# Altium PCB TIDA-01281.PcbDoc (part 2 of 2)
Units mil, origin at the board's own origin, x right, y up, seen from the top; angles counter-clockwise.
Board outline 2559.06 x 2165.35 mil, 4 copper layers (Top Layer, GND, SIGNAL, Bottom Layer), stack 60.234 mil thick; 109 components, 85 nets, 348 pads, 231 vias.
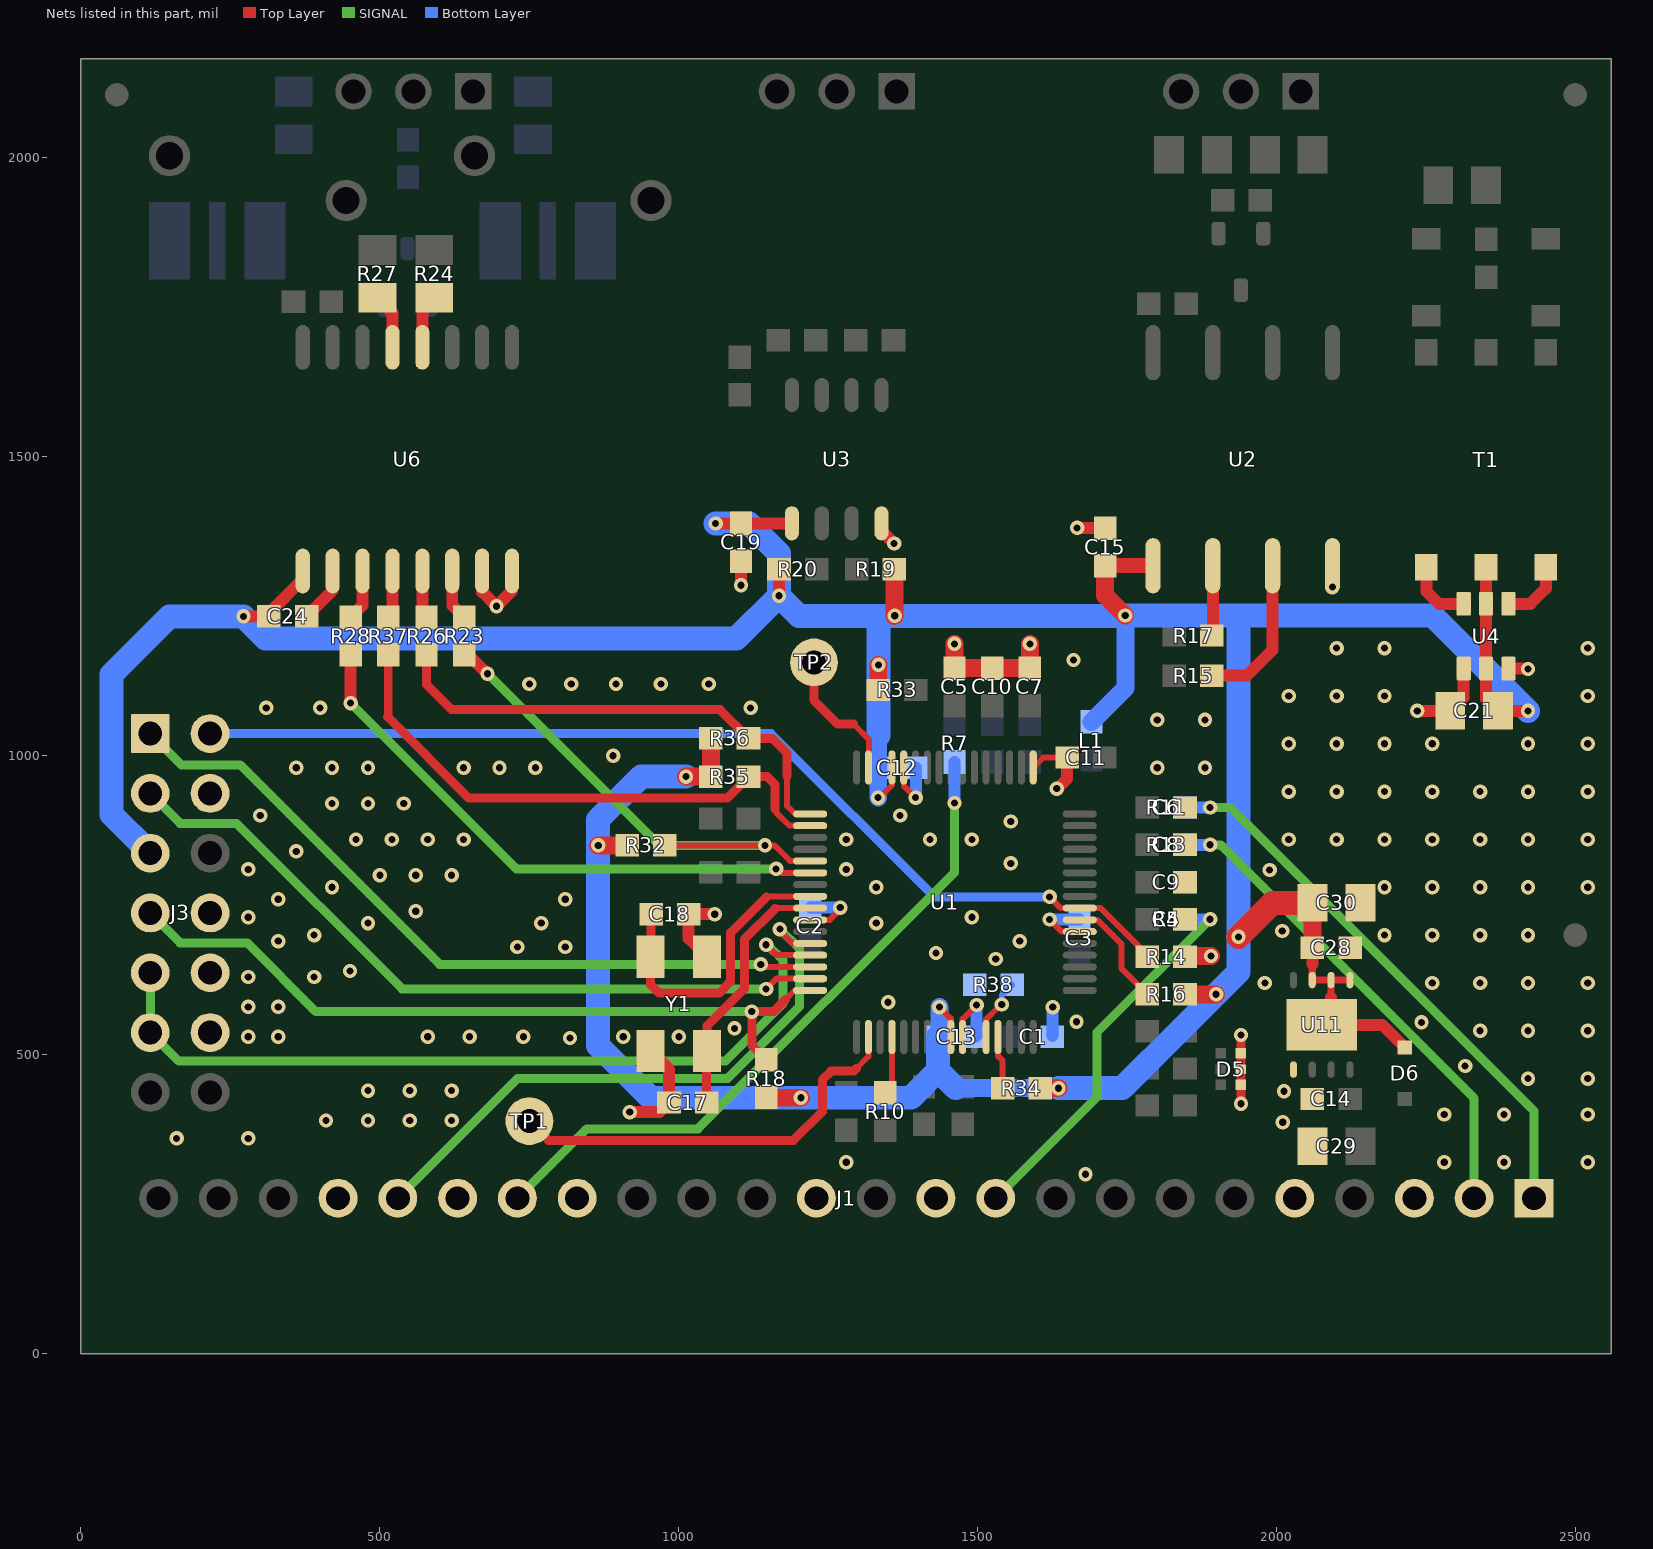
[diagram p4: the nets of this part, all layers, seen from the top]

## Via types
v1: diameter 24, hole 12, Top Layer to Bottom Layer, 231 vias

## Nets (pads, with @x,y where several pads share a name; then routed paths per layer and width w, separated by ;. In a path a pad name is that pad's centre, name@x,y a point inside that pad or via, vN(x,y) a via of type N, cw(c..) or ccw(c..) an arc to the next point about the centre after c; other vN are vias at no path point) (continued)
NetR10_1: R10.1 U1.52 | length 97.8
  Top Layer w10: R10.1@1345,436.5 1356.42,447.91 U1.52@1356.42,529.61
NetR15_2: R15.2 U2.3 | length 260.2
  Top Layer w20: R15.2@1891.5,1134 1950,1134 1993,1177 U2.3@1993,1317.85
NetR16_1: R16.1 U1.7 | length 188.6
  Top Layer w10: U1.7@1670.39,725.47 1699.91,725.47 1740,685.38 1740,644.5 R16.1@1783.5,601
NetR17_2: R17.2 U2.2 | length 117.5
  Top Layer w20: R17.2@1891.5,1201 1893,1202.51 U2.2@1893,1317.85
NetR23_1: R23.1 U6.6 | length 85.8
  Top Layer w20: U6.6@621,1308.99 621,1251.5 R23.1@641,1231.5
NetR24_1: R24.1 U6.12 | length 91.3
  Top Layer w20: U6.12@571,1683.01 571,1746 R24.1@591,1766
NetR26_1: R26.1 U6.5 | length 80.4
  Top Layer w20: U6.5@571,1308.99 571,1238.5 R26.1@578,1231.5
NetR27_1: R27.1 U6.13 | length 93.3
  Top Layer w20: R27.1@496,1766 521,1741 U6.13@521,1683.01
NetR28_1: R28.1 U6.3 | length 85.8
  Top Layer w20: R28.1@451,1231.5 471,1251.5 U6.3@471,1308.99
NetR34_1: R34.1 U1.61 | length 88.9
  Top Layer w10: U1.61@1533.58,529.61 1533.58,498.32 1541.5,490.4 R34.1@1541.5,444
NetR37_1: R37.1 U6.4 | length 80.4
  Top Layer w20: R37.1@514,1231.5 521,1238.5 U6.4@521,1308.99
NetR38_1: R38.1 U1.60 | length 109.2
  Top Layer w10: U1.60@1513.9,529.61 1513.9,559.26 1533.64,579 1534,579 v1@1536,581 ; v1@1538,582 v1@1537,582 ; v1(1540,584) 1539,584 v1@1537,582 ; v1@1536,581 1536,582 v1@1537,582 ; v1@1536,581 v1@1537,582
  Bottom Layer w10: v1(1540,584) 1540,599.5 R38.1@1557.5,617
NetT1_1: T1.1 U4.3 | length 111.3
  Top Layer w20: T1.1@2250,1315.08 2250,1275 2270.87,1254.13 U4.3@2312.6,1254.13
NetT1_3: T1.3 U4.1 | length 108.4
  Top Layer w20: U4.1@2387.4,1254.13 2424.13,1254.13 2450,1280 T1.3@2450,1315.08
NetTP1_1: TP1.1 U1.50 | length 706.5
  Top Layer w10: 1297,477 1317.05,497.05 U1.50@1317.05,529.61
  Top Layer w15: TP1.1@750,389 782.37,356.63 1191.63,356.63 1240,405 1240,458 1254.63,472.63 1292.63,472.63 1297,477 ; TP1.1@750,395 TP1.1@753,392
NetTP2_1: TP2.1 U1.31 | length 229.1
  Top Layer w10: 1292,1053 1317.74,1027.26 1317.74,981.08 U1.31@1317.05,980.39
  Top Layer w15: TP2.1@1226,1156 1226,1093 1266,1053 1292,1053
RS485_DE: R35.2 R37.2 U1.34 | length 940.9
  Top Layer w10: 1163.13,910.72 1163.13,904.88 1185.05,882.95 U1.34@1219.61,882.95
  Top Layer w15: R37.2@514,1168.5 514,1066 513,1065 649,929 1027.38,929 1027.45,929.08 1080.57,929.08 R35.2@1116.5,965 1147.63,965 1160.63,952 1160.63,910.72
RS485_REN: R26.2 R36.2 U1.33 | length 832.3
  Top Layer w10: 1181,966 1181,916 1194.36,902.64 U1.33@1219.61,902.64
  Top Layer w15: R26.2@578,1168.5 578,1119 620,1077 1068.5,1077 R36.2@1116.5,1029 1156,1029 1181,1004 1181,966
RS485_RX: R28.2 U1.38 | length 973.5
  Top Layer w10: v1@1162.71,817.3 v1(1162.71,810.71) 1163,811 1166,811 1172.79,804.21 U1.38@1219.61,804.21
  Top Layer w20: v1(451,1088) R28.2@451,1168.5
  SIGNAL w15: v1(451,1088) 728.29,810.71 v1(1162.71,810.71)
RS485_TX: R23.2 R32.2 U1.37 | length 888.9
  Top Layer w10: R32.2@976.5,850 v1(1144,850) 1160,850 1186.1,823.9 U1.37@1219.61,823.9
  Top Layer w20: R23.2@641,1168.5 647.99,1168.5 679.5,1137 v1(680,1137)
  SIGNAL w15: v1(680,1137) 967,850 v1(1144,850)
SGND: C1.2 C2.2 C3.1 C4.2 C5.2 C6.2 C7.2 C8.2 C9.2 C10.2 C11.2 C12.2 C13.2 C14.1 C15.2 C17.2 C18.2 C19.2 C21.1 C24.2 C28.1 C29.1 C30.1 D5.4 D5.5 D5.6 J1.3 J1.5 J1.11 J1.13 J1.17 J1.19 J1.21 J3.4 J3.8 J3.10 J3.12 R14.2 R38.2 U1.6 U1.17 U1.28 U1.42 U1.58 U2.4 U3.4 U4.4 U4.6 U6.2 U6.7 U6.8 U11.1 Y1.2 Y1.4 | length 1918.8
  Top Layer w8: v1@1266,746 v1(1270,746) v1@1270,743
  Top Layer w10: U1.42@1219.61,725.47 1252.47,725.47 v1@1270,743 ; U1.28@1376.1,980.39 1376.1,949.9 v1(1396,930) ; U1.58@1474.53,529.61 1474.53,559.12 ; v1@1495.02,579.61 1474.53,559.12 ; v1(1498,583) 1474.53,559.53 1474.53,559.12 ; U1.17@1592.64,980.39 1609.24,997 C11.2@1649.5,997 ; v1(1620,726) 1640.21,705.79 U1.6@1670.39,705.79
  Top Layer w15: v1(1940,418) 1940,449.16 D5.4@1939.73,449.43 D5.5@1939.73,476 D5.6@1939.73,502.57 1940,502.84 v1(1940,533)
  Top Layer w20: C24.2@377.5,1233 421,1276.51 U6.2@421,1308.99 ; U6.7@671,1308.99 671,1274 v1(695,1250) 721,1276 U6.8@721,1308.99 ; v1(918,404) 967.5,404 C17.2@983.5,420 983.5,475.51 Y1.4@952.76,506.26 ; Y1.2@1047.25,663.74 1016.5,694.49 C18.2@1016.5,735 v1(1060,735) ; v1(1104,1285) C19.2@1104,1325.51 ; U3.4@1339,1388.72 1339,1376 v1(1360,1355) ; v1(1632,945) v1@1633,945 ; v1@1634,945 v1@1633,945 ; C11.2@1649.5,997 1649.5,961.5 v1@1633,945 ; v1(1666.01,1381) 1665.5,1380.5 C15.2@1713,1380.5 ; v1(2093,1282) U2.4@2093,1352.85 ; v1(2235,1075) C21.1@2290,1075 2312.6,1097.6 U4.4@2312.6,1145.87 ; U4.6@2387.4,1145.87 2419.13,1145.87 v1(2420,1145)
  Top Layer w30: v1(1461,1187) C5.2@1461,1146.5 C10.2@1524,1146.5 C7.2@1587,1146.5 v1(1587,1187) ; R14.2@1846.5,664 1847.5,665 v1(1890,665)
  Bottom Layer w10: C13.2@1498.15,529.61 C13.2@1498.15,530
  Bottom Layer w20: C2.2@1220,746.5 1269.5,746.5 v1(1270,746) ; v1@1396.5,930.5 C12.2@1396.5,980 ; C13.2@1496.5,530 1498,531.5 v1(1498,583) ; v1(1620,726) 1620.5,726.5 C3.1@1670,726.5 ; C1.2@1625.13,531 v1@1625.13,579.45
  other v1: 1680,300 1280,320 2280,320 2380,320 2520,320 160,360 280,360 2010,387 410,390 480,390 550,390 620,390 2280,400 2380,400 2520,400 2012,439 480,440 550,440 620,440 2420,460 2520,460 2315,481 818,528 280,530 330,530 580,530 650,530 740,530 907,530 1000,530 2340,540 2420,540 2520,540 1093,544 2242,554 1665,555 1625.29,579.61 280,580 330,580 1350,587.68 1980,620 2260,620 2340,620 2420,620 2520,620 280,630 390,630 450,640 1530,660 1430,670 730,680 810,680 330,690 1570,690 390,700 2180,700 2260,700 2340,700 2420,700 2009,707 480,720 770,720 1330,720 280,730 1490,730 560,740 330,760 810,760 420,780 1330,780 2180,780 2260,780 2340,780 2420,780 2520,780 500,800 560,800 620,800 1988,809 280,810 1280,810 1555,820 360,840 460,860 520,860 580,860 640,860 1280,860 1420,860 1490,860 2020,860 2100,860 2180,860 2260,860 2340,860 2420,860 2520,860 1555,890 300,900 1370,900 420,920 480,920 540,920 2020,940 2100,940 2180,940 2260,940 2340,940 2420,940 2520,940 360,980 420,980 480,980 640,980 700,980 760,980 1800,980 1880,980 890,1000 2020,1020 2100,1020 2180,1020 2260,1020 2420,1020 2520,1020 1800,1060 1880,1060 310,1080 400,1080 1120,1080 2020,1100 2100,1100 2180,1100 2520,1100 750,1120 820,1120 895,1120 970,1120 1050,1120 1660,1160 2100,1180 2180,1180 2520,1180
TCK: J3.9 J3.11 U1.45 | length 1410.4
  Top Layer w10: v1(1146,684) 1163.58,666.42 U1.45@1219.61,666.42
  SIGNAL w15: J3.9@116,637 J3.11@116,537 163.86,489.15 1077.86,489.15 1174.37,585.66 1174.37,657.75 1148.13,684 v1(1146,684)
TDI: J3.3 U1.47 | length 1246.1
  Top Layer w10: v1(1146,610) 1163.05,627.05 U1.47@1219.61,627.05
  SIGNAL w15: J3.3@116,937 166,887 260,887 537,610 v1(1146,610)
TDO: J3.7 R18.1 U1.48 | length 1260.9
  Top Layer w10: 1178,592 1193.36,607.36 U1.48@1219.61,607.36
  Top Layer w15: v1(1122,572) 1122,515.5 R18.1@1139.5,498 ; v1@1129,572 1158.13,572 1178.06,591.94
  SIGNAL w15: J3.7@116,737 166,687 278,687 393,572 v1(1122,572)
TEMP1: J1.10 R5.1 | length 656.9
  SIGNAL w15: J1.10@1530,260 1699.13,429.13 1699.13,537.13 v1(1888.46,726.46)
  Bottom Layer w20: R5.1@1846.5,726.46 v1(1888.46,726.46)
TEMP2: J1.20 U1.44 | length 1009.9
  Top Layer w10: v1(1169,710) 1169,707 1189.9,686.1 U1.44@1219.61,686.1
  SIGNAL w15: J1.20@530,260 730.37,460.37 1081.44,460.37 1202,580.94 1202,677 v1(1169,710)
TMS: J3.1 U1.46 | length 1265.3
  Top Layer w10: v1(1137,651) 1141.27,646.73 U1.46@1219.61,646.73
  SIGNAL w15: J3.1@116,1037 168.15,984.86 266.14,984.86 600,651 v1(1137,651)
TRST: J3.2 R14.1 U1.8 | length 1737
  Top Layer w10: v1(1620,764) 1638.84,745.16 U1.8@1670.39,745.16 1705.5,745.16 R14.1@1795,655.66
  Bottom Layer w15: J3.2@216,1037 1154,1037 1427,764 v1(1620,764)
VBAT_S: J1.1 R11.1 | length 939.7
  SIGNAL w15: v1(1888.46,913.46) 1922.54,913.46 2430,406 J1.1@2430,260
  Bottom Layer w20: R11.1@1846.5,913.46 v1(1888.46,913.46)
VBOOST_S: J1.2 R13.1 | length 826.1
  SIGNAL w15: v1(1888.46,851) 1906,851 2330,427 J1.2@2330,260
  Bottom Layer w20: R13.1@1846.5,851 v1(1888.46,851)
VBUS_S: J1.18 R7.1 | length 1141.2
  SIGNAL w15: J1.18@730,260 846,376 1032,376 1461,805 v1(1461,921)
  Bottom Layer w20: v1(1461,921) R7.1@1461,989.5
VDD: C12.1 C13.1 C15.1 C19.1 C21.2 C24.1 C28.2 C30.2 D6.2 J3.5 L1.1 R16.2 R18.2 R19.1 R20.1 R32.1 R33.1 R34.2 R35.1 R36.1 T1.2 U1.29 U1.57 U2.1 U3.1 U4.2 U4.5 U6.1 U11.5 U11.6 U11.7 U11.9 | length 7961
  Top Layer w10: v1(1333.01,930) 1335.54,930 1356.42,950.88 U1.29@1356.42,980.39 ; v1(1435.65,579.61) 1454.84,560.42 U1.57@1454.84,529.61 ; C30.2@2059.5,753.5 C30.2@2060,754 ; U11.9@2088,550 2090.75,552.75 U11.9@2090.75,565.75
  Top Layer w12: 2059.25,651.73 U11.7@2059.25,624.8 U11.6@2090.75,624.8 ; 2090.75,596 U11.6@2090.75,624.8 ; U11.5@2122.24,624.8 U11.6@2090.75,624.8
  Top Layer w20: v1(272,1233) C24.1@314.5,1233 314.5,1238.5 371,1295 U6.1@371,1308.99 ; v1(1061.5,1388.5) C19.1@1104,1388.5 1104.22,1388.72 U3.1@1189,1388.72 ; v1(1167.5,1267.5) R20.1@1167.5,1312 ; C15.1@1713,1317.5 C15.1@1713.35,1317.85 ; U2.1@1793,1317.85 U2.1@1793,1352.85 ; 2059.25,651.73 2059.5,651.99 C28.2@2059.5,679 ; U11.9@2075,550 2090.75,565.75 2090.75,596 ; U11.9@2088,550 2176.31,550 D6.2@2214,512.31 ; T1.2@2350,1315.08 U4.2@2350,1254.13 U4.5@2350,1145.87 2350,1095 C21.2@2370,1075 v1(2420,1075)
  Top Layer w25: C15.1@1713.35,1317.85 U2.1@1793,1317.85
  Top Layer w30: v1(865.06,850) R32.1@913.5,850 ; v1(1012,965) R35.1@1053.5,965 R36.1@1053.5,1029 ; R18.2@1146,428.51 1146.51,428 v1(1204,428) ; R33.1@1333.5,1110 1333.5,1151.5 v1(1334,1152) ; R19.1@1360.5,1312 1360.5,1234.5 v1(1361,1234) ; v1@1624.5,444 v1(1635,444) ; C15.1@1713,1317.5 1713,1267.99 v1(1746.5,1234.5) ; R16.2@1846.5,601 v1(1898.54,601) ; C28.2@2059.5,679 C30.2@2059.5,753.5
  Top Layer w40: v1(1936,697) 1993,754 C30.2@2060,754
  Bottom Layer w20: 1842.54,545 1842.69,545
  Bottom Layer w25: C13.1@1433.5,530 C13.1@1435.65,532.15
  Bottom Layer w30: v1@1333.5,930.5 C12.1@1333.5,980 1333.5,1033.5 ; C13.1@1435.65,532.15 v1(1435.65,579.61) ; 1463.01,444 v1(1635,444) ; L1.1@1690,1056.5 1746.87,1113.37 1746.87,1234.12 v1(1746.5,1234.5)
  Bottom Layer w40: J3.5@116,837 51,902 51,1136 148,1233 v1(272,1233) 309,1196 1096,1196 v1(1167.5,1267.5) ; v1(1012,965) 937.06,965 865.06,893 v1(865.06,850) 865.06,515.55 952.61,428 1388,428 1433.5,473.5 ; v1(1061.5,1388.5) 1117.5,1388.5 1167.5,1338.5 v1(1167.5,1267.5) ; 1333.5,1033.5 1334,1034 v1(1334,1152) 1334,1233 1333,1234 ; C13.1@1433.5,530 1433.5,473.5 ; 1463.01,444 1433.5,473.5 ; v1(1635,444) 1695,444 1741.54,444 1842.54,545 v1(1898.54,601) 1936,638.46 v1(1936,697) 1936,1229.5 1941,1234.5 ; v1(2420,1075) 2260.5,1234.5 1941,1234.5 ; v1(1167.5,1267.5) 1201,1234 1333,1234 ; 1333,1234 v1(1361,1234) 1746,1234 v1(1746.5,1234.5) 1941,1234.5
X1: C17.1 U1.41 Y1.1 | length 430.9
  Top Layer w10: 1160.81,744.81 1161.16,745.16 U1.41@1219.61,745.16
  Top Layer w15: C17.1@1046.5,420 1046.5,505.51 Y1.1@1047.25,506.26 1047.25,548.25 1109.63,610.63 1109.63,692.94 1161.16,744.47
X2: C18.1 U1.40 Y1.3 | length 505.9
  Top Layer w10: 1146.5,764.5 1146.84,764.84 U1.40@1219.61,764.84
  Top Layer w15: C18.1@953.5,735 953.5,664.49 Y1.3@952.76,663.74 952.76,617.25 967,603 1067.3,603 1086.75,622.45 1086.75,704.06 1146.84,764.15
pads on no net: FID1.1 FID2.1 FID3.1 FID4.1 FID5.1 FID6.1 J3.6 J3.13 J3.14 U1.4 U1.9 U1.14 U1.15 U1.18 U1.19 U1.21 U1.24 U1.30 U1.36 U1.53 U1.55 U1.62 U1.63 U1.64 U5.2 U6.11 U6.14 U7.2 U11.8

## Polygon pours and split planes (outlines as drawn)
SGND on GND "M9 Title Sheet-No Net" (solid, remove dead copper, pour order 12): 0,235 0,75 75,0 1925,0 2469.06,0 2559.06,90 2559.06,1364.95 2503,1421 58,1421 0,1363
COMM_GND on GND "M9 Title Sheet-No Net" (solid, remove dead copper, pour order 16): 155,2165 70,2165 0,2095 0,1636 63,1573 2486,1573 2559.06,1646.06 2559.06,2095.95 2490,2165
SGND on Top Layer "M9 Title Sheet-No Net" (solid, remove dead copper, pour order 11): 0,235 0,75 75,0 1925,0 2469.06,0 2559.06,90 2559.06,1364.95 2503,1421 58,1421 0,1363
COMM_GND on Top Layer "M9 Title Sheet-No Net" (solid, remove dead copper, pour order 15): 155,2165 70,2165 0,2095 0,1636 63,1573 2486,1573 2559.06,1646.06 2559.06,2095.95 2490,2165
SGND on SIGNAL "M9 Title Sheet-No Net" (solid, remove dead copper, pour order 10): 0,235 0,75 75,0 1925,0 2469.06,0 2559.06,90 2559.06,1364.95 2503,1421 58,1421 0,1363
COMM_GND on SIGNAL "M9 Title Sheet-No Net" (solid, remove dead copper, pour order 14): 155,2165 70,2165 0,2095 0,1636 63,1573 2486,1573 2559.06,1646.06 2559.06,2095.95 2490,2165
SGND on Bottom Layer "M9 Title Sheet-No Net" (solid, remove dead copper, pour order 9): 0,235 0,75 75,0 1925,0 2469.06,0 2559.06,90 2559.06,1364.95 2503,1421 58,1421 0,1363
COMM_GND on Bottom Layer "M9 Title Sheet-No Net" (solid, remove dead copper, pour order 13): 155,2165 70,2165 0,2095 0,1636 63,1573 2486,1573 2559.06,1646.06 2559.06,2095.95 2490,2165

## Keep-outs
Keep-Out Layer:
  lines w10: 2558.11,0 2559.06,0.94 ; 0,0 0,2165.36 2559.06,2165.36 2559.06,0 0,0 ; 4730,3149.49 cw(c4730,3144.49) 4735,3144.49 ccw(c4730,3144.49) 4730,3149.49

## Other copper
Top Layer:
  text ".Layer_Name" at 357,-1164 h60
GND:
  text ".layer_Name" at 350,-1160 h60
SIGNAL:
  text ".layer_Name" at 360,-1160 h60
Bottom Layer:
  text ".Layer_Name" at 357,-1164 h60

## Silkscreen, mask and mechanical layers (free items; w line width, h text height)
Top Overlay:
  lines w6: 1884,576 1889,576 1891,576 ; 1909,407 1909,424 ; 2002,412 2020,412 ; 2385,1899 2409,1923 2421,1923 ; 1892,435 1953,435 1954,435 1954,516 1954,517 1892,517 1892,496 1892,435
  text "TIDA-01281-E1" at 1093,29 h60
  text ".Layer_Name" at 357,-1164 h60
Bottom Overlay:
  circle w10: c2490,260 r10
  text ".Layer_Name" at 357,-1164 h60
Top Paste:
  text ".Layer_Name" at 357,-1164 h60
Bottom Paste:
  text ".Layer_Name" at 357,-1164 h60
Top Solder:
  text ".Layer_Name" at 357,-1164 h60
  text ".Layer_Name" at 357,-1164 h60
Bottom Solder:
  text ".Layer_Name" at 357,-1164 h60
M1 Board Outline:
  the board outline again, w10
M2 Board Dimensions:
  rectangle: -95,-705.51 280,-580.51
  rectangle: -220,-580.51 -95,-455.51
  lines w7: -220,-580.51 780,-580.51 ; -95,-705.51 -95,-455.51 ; 30,-705.51 30,-455.51 ; 280,-705.51 280,-455.51 ; 530,-705.51 530,-455.51 ; -220,-705.51 -220,-455.51 780,-455.51 780,-705.51 -220,-705.51
M3 3D STEP Top:
  text ".Layer_Name" at 357,-1164 h60
M4 3D STEP Bottom:
  text ".Layer_Name" at 357,-1164 h60
M5 Assembly Top:
  circle w10: c1885.97,503 r1
  lines w10: -512,-1235.68 6088,-1235.68 ; -512,-1032.34 6090,-1032.34 ; -512,-829.01 -512,-1439.01 3493,-1439.01 6090,-1439.01 6090,-829.01 -511.5,-829.01 -511.5,-1439.01 1064,-1439.01 ; 1953,-1439.01 1953,-829.01 ; 3220,-1032.34 3220,-829.01 ; 4060,-1032.34 4060,-829.01 ; 4682,-1445.51 4682,-1242.68
  text "COMPONENTS MARKED 'DNP' SHOULD NOT BE POPULATED." at 933.5,-624.01 h60
  text "ASSEMBLY VARIANT:" at 933,-739.51 h60
  text ".VariantName" at 1969,-739.51 h60
  text "PCB VIEWED FROM TOP SIDE" at -448.5,-961.18 h60
  text "BOARD #:" at 2028,-961.18 h60
  text ".PRJ_Number" at 2573.5,-961.18 h60
  text "REV:" at 3418,-961.18 h60
  text ".PCB_Rev" at 3709.5,-961.18 h60
  text "SVN REV:" at 4256,-961.18 h60
  text ".VersionControl_RevNumber" at 4762,-961.18 h60
  text ".layer_Name" at 350,-1160 h60
  text "TID #:" at 2028,-1164.51 h60
  text ".TID" at 2573.5,-1164.51 h60
  text "PLOT NAME =" at -448.5,-1369.85 h60
  text ".plot_File_Name" at 357,-1369.85 h60
  text "GENERATED    :" at 2030,-1369.85 h60
  text ".Print_Date" at 2899.5,-1369.85 h60
  text ".Print_Time" at 3628.5,-1369.85 h60
  text "TEXAS INSTRUMENTS" at 4893,-1369.85 h60
M6 Assembly Bottom:
  circle w10: c2490,260 r10
  lines w10: -512.5,-1032.84 6089.5,-1032.84 ; -510.5,-1236.18 6089.5,-1236.18 ; 895.5,-1446.01 895.5,-1243.18 ; 1517.5,-1032.84 1517.5,-829.51 ; 2357.5,-1032.84 2357.5,-829.51 ; 3624.5,-1439.51 3624.5,-829.51 ; 4513.5,-1439.51 6089,-1439.51 6089,-829.51 -512.5,-829.51 -512.5,-1439.51 2084.5,-1439.51 6089.5,-1439.51 6089.5,-829.51
  text "COMPONENTS MARKED 'DNP' SHOULD NOT BE POPULATED." at 5882,-623.51 h60
  text ".VariantName" at 4838,-739.51 h60
  text "ASSEMBLY VARIANT:" at 5877,-739.51 h60
  text ".VersionControl_RevNumber" at 815.5,-961.68 h60
  text "SVN REV:" at 1321.5,-961.68 h60
  text ".PCB_Rev" at 1868,-961.68 h60
  text "REV:" at 2159.5,-961.68 h60
  text ".PRJ_Number" at 3004,-961.68 h60
  text "BOARD #:" at 3549.5,-961.68 h60
  text "PCB VIEWED FROM BOTTOM SIDE" at 6026,-961.68 h60
  text ".layer_Name" at 5090,-1160 h60
  text ".TID" at 3004,-1165.01 h60
  text "TID #:" at 3549.5,-1165.01 h60
  text "TEXAS INSTRUMENTS" at 684.5,-1370.35 h60
  text ".Print_Time" at 1949,-1370.35 h60
  text ".Print_Date" at 2678,-1370.35 h60
  text "GENERATED    :" at 3547.5,-1370.35 h60
  text ".plot_File_Name" at 5220.5,-1370.35 h60
  text "PLOT NAME =" at 6026,-1370.35 h60
M9 Title Sheet:
  drawing of 57 lines, arcs and shapes, not listed
  text "1" at 519.84,7730.99 h70
  text "2" at 3015.5,7730.99 h70
  text "3" at 5504.84,7730.99 h70
  text "4" at 8011.51,7730.99 h70
  text "5" at 10510.5,7730.99 h70
  text "6" at 13015.5,7730.99 h70
  text "A" at -636.5,6587.99 h70
  text "A" at 14163.5,6587.99 h70
  text "B" at -636.5,4207.99 h70
  text "B" at 14163.5,4207.99 h70
  text "C" at -636.5,1832.99 h70
  text "C" at 14163.5,1832.99 h70
  text "PROJECT TITLE:" at 11123.5,-28.01 h45
  text ".PRJ_Title" at 11173.5,-161.34 h70
  text "DESIGNED FOR:" at 11123.5,-329.01 h45
  text ".PRJ_Customer" at 11173.5,-469.01 h70
  text "D" at -636.5,-537.01 h70
  text "D" at 14163.5,-537.01 h70
  text "FILE NAME:" at 11123.5,-629.01 h45
  text ".PCB_File_Name_No_Path" at 11173.5,-749.01 h70
  text "Texas Instruments (TI) and/or its licensors do not warrant the accuracy or completeness of this specification" at 6154,-910.85 h45
  text "ENGINEER:" at 11123.5,-919.01 h45
  text "LAYOUT BY:" at 12628.5,-919.01 h45
  text "or any information contained therein. TI and/or its licensors do not warrant that this design will meet" at 6109.02,-1023.51 h45
  text ".PRJ_Engineer" at 11173.5,-1074 h70
  text ".PCB_Layout" at 12679,-1074 h70
  text "the specifications, will be suitable for your application or fit for any particular purpose, or will operate in" at 6109.02,-1136.18 h45
  text "ALTIUM DESIGNER VERSION:" at 12628.5,-1229.01 h45
  text "an implementation. TI and/or its licensors do not warrant that the design is production worthy. You should" at 6109.02,-1248.85 h45
  text "completely validate and test your design implementation to confirm the system functionality for your application." at 6154,-1361.51 h45
  text ".print_Scale" at 11173.5,-1362.34 h70
  text ".Application_BuildNumber" at 12679,-1362.34 h70
  text "1" at 519.84,-1569.01 h70
  text "2" at 3015.5,-1569.01 h70
  text "3" at 5504.84,-1569.01 h70
  text "4" at 8011.51,-1569.01 h70
  text "5" at 10510.5,-1569.01 h70
  text "6" at 13015.5,-1569.01 h70
M10 Fab Notes:
  drawing of 191 lines, arcs and shapes, not listed
  text "DESIGN INFORMATION" at 12166.52,6384.49 h60
  text "(REFER ALSO ARRAY/PANEL PROFILING INFORMATION)" at 11804.96,6222.77 h60
  text "BOARD SIZE" at 11118.96,6218.49 h60
  text "X" at 12086.96,6090.67 h60
  text "55MM" at 12322.5,6083.49 h60
  text "65MM" at 11635,6080 h60
  text "Number of Layers :" at 11536.96,5983.49 h60
  text "4" at 12631.77,5973.49 h60
  text "MIN. TRACK WIDTH:" at 11536.96,5844.49 h60
  text "10" at 12606.5,5844.89 h60
  text "MIL" at 12787.96,5844.49 h60
  text "MIN. CLEARANCE:" at 11536.96,5712.49 h60
  text "7.87" at 12555,5712 h60
  text "MIL" at 12805.5,5685.89 h60
  text "MIN. VIA PAD SIZE:" at 11536.96,5580.49 h60
  text "24" at 12617.5,5580.89 h60
  text "MIL" at 12805.5,5557.89 h60
  text "0.15mm (6MIL)" at 12231.96,5438.78 h60
  text "EXTERNAL" at 12968.5,5438.89 h60
  text "MINIMUM ANNULAR RING" at 11207.73,5434.49 h60
  text "PER" at 11407.73,5316.49 h60
  text "IPC-D-275 CLASS 2 LEVEL C" at 11627.73,5316.49 h60
  text "MIL, HOLES" at 13115.96,5204.2 h60
  text "+/-" at 12723.5,5203.49 h60
  text "+/-" at 13577.5,5203.49 h60
  text "REGISTRATION TOLERANCES:" at 11207.73,5198.49 h60
  text "METAL" at 12407.5,5198.49 h60
  text "5" at 12983.7,5198.49 h60
  text "3" at 13816.7,5198.49 h60
  text "MIL" at 13932.96,5198.49 h60
  text "IMPEDENCE CONTROLLED BOARD:NO" at 11240.5,5049.49 h60
  text "MATERIAL:" at 11116.96,4826.03 h60
  text "FR-4 High Tg" at 12103.4,4685.7 h60
  text "FR-408" at 11537.96,4677.13 h60
  text "OTHER" at 13025.96,4677.13 h60
  text "X" at 11941.5,4675.49 h60
  text "THICKNESS:" at 11118.5,4520.49 h60
  text "63 MIL (1.6mm) +/-10%" at 11777.5,4515.49 h60
  text "OTHER" at 13142.96,4510.13 h60
  text "X" at 11642.5,4507.49 h60
  text "TOLERANCE:" at 11191.73,4352.13 h60
  text "X" at 12031.04,4352.13 h60
  text "ANSI IPC-6012 TYPE 3 CLASS 2" at 12217.98,4352.13 h60
  text "OTHER +/-" at 12217.96,4196.13 h60
  text "BOW & TWIST:" at 11191.73,4039.13 h60
  text "X" at 12031.04,4039.13 h60
  text "ANSI IPC-6012 TYPE 3 CLASS 2" at 12217.98,4039.13 h60
  text "OTHER +/-" at 12217.96,3880.62 h60
  text "DRILLING:" at 11116.96,3742.13 h60
  text "REFERENCE:" at 11191.73,3625.13 h60
  text "X" at 11839.96,3625.13 h60
  text "AS SHOWN" at 12026.96,3625.13 h60
  text "X" at 12740.96,3625.13 h60
  text "NC_DRILL FILES" at 12877.96,3625.13 h60
  text "PTH MIN COPPER THICKNESS:" at 11191.73,3467.13 h60
  text "X" at 12541.96,3467.13 h60
  text "1MIL" at 12678.96,3467.13 h60
  text "OTHER" at 13175.96,3467.13 h60
  text "BOARD FINISH:" at 11116.96,3308.13 h60
  text "SILKSCREEN:" at 11272.18,3190.13 h60
  text "X" at 12220.96,3190.13 h60
  text "TOP" at 12346.96,3190.13 h60
  text "X" at 12730.96,3190.13 h60
  text "BOTTOM" at 12857.96,3190.13 h60
  text "SILKSCREEN COLOR:" at 11272.18,3023.13 h60
  text "X" at 12219.92,3023.13 h60
  text "WHITE" at 12346.96,3023.13 h60
  text "OTHER" at 12857.96,3023.13 h60
  text "SOLDER RESIST COLOR:" at 11272.18,2853.13 h60
  text "X" at 11839.92,2693.93 h60
  text "GREEN" at 11966.96,2693.93 h60
  text "BLUE" at 12557.96,2693.93 h60
  text "OTHER" at 13095.96,2693.93 h60
  text "IMMERSION GOLD (ENIG)" at 12177.96,2505.41 h60
  text "ENEPIG" at 13515.5,2502.13 h60
  text "SURFACE FINISH:" at 11116.96,2501.13 h60
  text "X" at 11991.01,2501.13 h60
  text "IMM. TIN/SILVER OR EQUIV" at 11446.5,2344.13 h60
  text "OTHER" at 12877.96,2344.13 h60
  text "ARRAY/PANEL:" at 11116.96,2165.13 h60
  text "CUT AND TRIM PER MECH LAYER 1" at 12177.96,2160.84 h60
  text "N.C. ROUTE" at 12177.96,2009.13 h60
  text "X" at 12856.96,2009.13 h60
  text "V. SCORE" at 13043.96,2009.13 h60
  text "CERTIFICATION:" at 11116.96,1872.13 h60
  text "MATERIALS AND WORKMANSHIP FOR ALL PCBS" at 11841.96,1872.13 h60
  text "TO MEET OR EXCEED THE REQUIREMENTS OF:" at 11841.96,1774.13 h60
  text "X" at 11468.46,1637.62 h60
  text "ANSI IPC-A-600F CLASS ->" at 11607.46,1637.62 h60
  text "X" at 13246.52,1637.62 h60
  text "2" at 13365.46,1637.62 h60
  text "1" at 13050.46,1636.13 h60
  text "3" at 13719.46,1636.13 h60
  text "X" at 11470.52,1478.13 h60
  text "UL 94V-0" at 11607.46,1478.13 h60
  text "X" at 12282.52,1478.13 h60
  text "RoHS" at 12419.46,1478.13 h60
  text "OTHER" at 13063.87,1478.13 h60
  text "PER ORDER" at 13460.92,1478.13 h60
  text "ADDITIONAL REQUIREMENTS:" at 11116.96,1337.13 h60
  text "MICROSECTION:" at 11191.73,1222.13 h60
  text "YES" at 12097.46,1222.13 h60
  text "REQUIRED" at 12958.96,1065.98 h60
  text "BARE BOARD ELEC. TEST:" at 11191.73,1063.13 h60
  text "NONE" at 12497.46,1063.13 h60
  text "X" at 12831.96,1063.13 h60
  text "PER ORDER" at 13550.96,1063.13 h60
  text "MANUFACTURER'S UL:" at 11191.73,906.13 h60
  text "RAIL" at 12357.46,901.84 h60
  text "METAL" at 12849.28,901.84 h60
  text "X" at 13224.5,901.49 h60
  text "SILK" at 13360.96,901.84 h60
  text "VIA`S TO BE TENTED:" at 11171.5,714.49 h60
  text "NO" at 12076.5,714.49 h60
M11 Gerber Information:
  lines w10: -512,-1235.68 6088,-1235.68 ; -512,-1032.34 6090,-1032.34 ; -512,-829.01 -512,-1439.01 3493,-1439.01 6090,-1439.01 6090,-829.01 -511.5,-829.01 -511.5,-1439.01 1064,-1439.01 ; 1953,-1439.01 1953,-829.01 ; 3220,-1032.34 3220,-829.01 ; 4060,-1032.34 4060,-829.01 ; 4682,-1445.51 4682,-1242.68
  text "ALL ARTWORK VIEWED FROM TOP SIDE" at -448.5,-961.18 h60
  text "BOARD #:" at 2028,-961.18 h60
  text ".PRJ_Number" at 2573.5,-961.18 h60
  text "REV:" at 3418,-961.18 h60
  text ".PCB_Rev" at 3709.5,-961.18 h60
  text "SVN REV:" at 4256,-961.18 h60
  text ".VersionControl_RevNumber" at 4762,-961.18 h60
  text "LAYER NAME =" at -448.5,-1164 h60
  text "TID #:" at 2028,-1164.51 h60
  text ".TID" at 2573.5,-1164.51 h60
  text "PLOT NAME =" at -448.5,-1369.85 h60
  text ".plot_File_Name" at 357,-1369.85 h60
  text "GENERATED    :" at 2030,-1369.85 h60
  text ".Print_Date" at 2899.5,-1369.85 h60
  text ".Print_Time" at 3628.5,-1369.85 h60
  text "TEXAS INSTRUMENTS" at 4893,-1369.85 h60
M12 Stackup:
  drawing of 295 lines, arcs and shapes, not listed
  text "Layer" at 6361,7367 h60
  text "Name" at 6770.91,7367 h60
  text "Material" at 7700.66,7367 h60
  text "Thickness" at 8560.42,7367 h60
  text "Constant" at 9210.26,7367 h60
  text "Board Layer Stack" at 9780.12,7367 h60
  text "1" at 6361,7247 h60
  text "Top Overlay" at 6770.91,7247 h60
  text "2" at 6361,7127 h60
  text "Top Solder" at 6770.91,7127 h60
  text "Solder Resist" at 7700.66,7127 h60
  text "0.40mil" at 8560.42,7127 h60
  text "3.5" at 9210.26,7127 h60
  text "3" at 6361,7007 h60
  text "Top Layer" at 6770.91,7007 h60
  text "Copper" at 7700.66,7007 h60
  text "0.70mil" at 8560.42,7007 h60
  text "4" at 6361,6887 h60
  text "Dielectric1" at 6770.91,6887 h60
  text "FR-4 High Tg" at 7700.66,6887 h60
  text "10.00mil" at 8560.42,6887 h60
  text "4.8" at 9210.26,6887 h60
  text "5" at 6361,6767 h60
  text "GND" at 6770.91,6767 h60
  text "Copper" at 7700.66,6767 h60
  text "1.42mil" at 8560.42,6767 h60
  text "6" at 6361,6647 h60
  text "Dielectric 2" at 6770.91,6647 h60
  text "FR-4 High Tg" at 7700.66,6647 h60
  text "36.00mil" at 8560.42,6647 h60
  text "4.2" at 9210.26,6647 h60
  text "7" at 6361,6527 h60
  text "SIGNAL" at 6770.91,6527 h60
  text "Copper" at 7700.66,6527 h60
  text "1.42mil" at 8560.42,6527 h60
  text "8" at 6361,6407 h60
  text "Dielectric 3" at 6770.91,6407 h60
  text "FR-4 High Tg" at 7700.66,6407 h60
  text "10.00mil" at 8560.42,6407 h60
  text "4.2" at 9210.26,6407 h60
  text "9" at 6361,6287 h60
  text "Bottom Layer" at 6770.91,6287 h60
  text "Copper" at 7700.66,6287 h60
  text "0.70mil" at 8560.42,6287 h60
  text "10" at 6361,6167 h60
  text "Bottom Solder" at 6770.91,6167 h60
  text "Solder Resist" at 7700.66,6167 h60
  text "0.40mil" at 8560.42,6167 h60
  text "3.5" at 9210.26,6167 h60
  text "11" at 6361,6047 h60
  text "Bottom Overlay" at 6770.91,6047 h60
M13 Component Bodies Top:
  text ".Layer_Name" at 357,-1164 h60
M14 Component Bodies Bottom:
  text ".Layer_Name" at 357,-1164 h60
M15 Courtyards Top:
  text ".Layer_Name" at 357,-1164 h60
M16 Courtyards Bottom:
  text ".Layer_Name" at 357,-1164 h60
Drill Drawing:
  lines w10: 4573.12,1220 4623.12,1220 4623.12,1270 4573.12,1270 4573.12,1220 ; 4573.12,1382.5 4585.62,1382.5 4598.12,1370 4610.62,1382.5 4623.12,1382.5 4610.62,1395 4623.12,1407.5 4610.62,1407.5 4598.12,1420 4585.62,1407.5 4573.12,1407.5 4585.62,1395 4573.12,1382.5 ; 4573.12,1532.5 4585.62,1532.5 4585.62,1520 4610.62,1520 4610.62,1532.5 4623.12,1532.5 4623.12,1557.5 4610.62,1557.5 4610.62,1570 4585.62,1570 4585.62,1557.5 4573.12,1557.5 4573.12,1532.5
  lines w15: 4505,1175 8383.97,1175 ; 4505,1625 8383.97,1625 ; 5055.88,1025 5055.88,1775 ; 5753.69,1025 5753.69,1775 ; 7099.29,1025 7099.29,1775 ; 7605.17,1025 7605.17,1775 ; 4505,1025 8383.97,1025 8383.97,1775 4505,1775 4505,1025
  text "Symbol" at 4595,1670 h72
  text "Hit Count" at 5100.88,1670 h72
  text "Finished Hole Size" at 5798.69,1670 h72
  text "Plated" at 7144.29,1670 h72
  text "Hole Type" at 7650.17,1670 h72
  text "4" at 5100.88,1520 h60
  text "45.28mil (1.150mm)" at 5798.69,1520 h60
  text "PTH" at 7144.29,1520 h60
  text "Round" at 7650.17,1520 h60
  text "49" at 5100.88,1370 h60
  text "40.00mil (1.016mm)" at 5798.69,1370 h60
  text "PTH" at 7144.29,1370 h60
  text "Round" at 7650.17,1370 h60
  text "231" at 5100.88,1220 h60
  text "12.00mil (0.305mm)" at 5798.69,1220 h60
  text "PTH" at 7144.29,1220 h60
  text "Round" at 7650.17,1220 h60
  text "284 Total" at 5100.88,1070 h60
  text "DRILL TABLE" at 5054.2,748.2 h60
  text "FOR 12MIL DRILL +0/-12MIL" at 5051,651 h60
  text "FOR PTH +3/-3MIL" at 5054,558 h60
  text "This is not impedence controlled board." at 5050,465 h60
  text ".Layer_Name" at 357,-1164 h60

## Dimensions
-220,-705.51 to 780,-705.51 on M2 Board Dimensions
0,0 to 2559.06,0 on M2 Board Dimensions
0,0 to 0,2165.36 on M2 Board Dimensions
